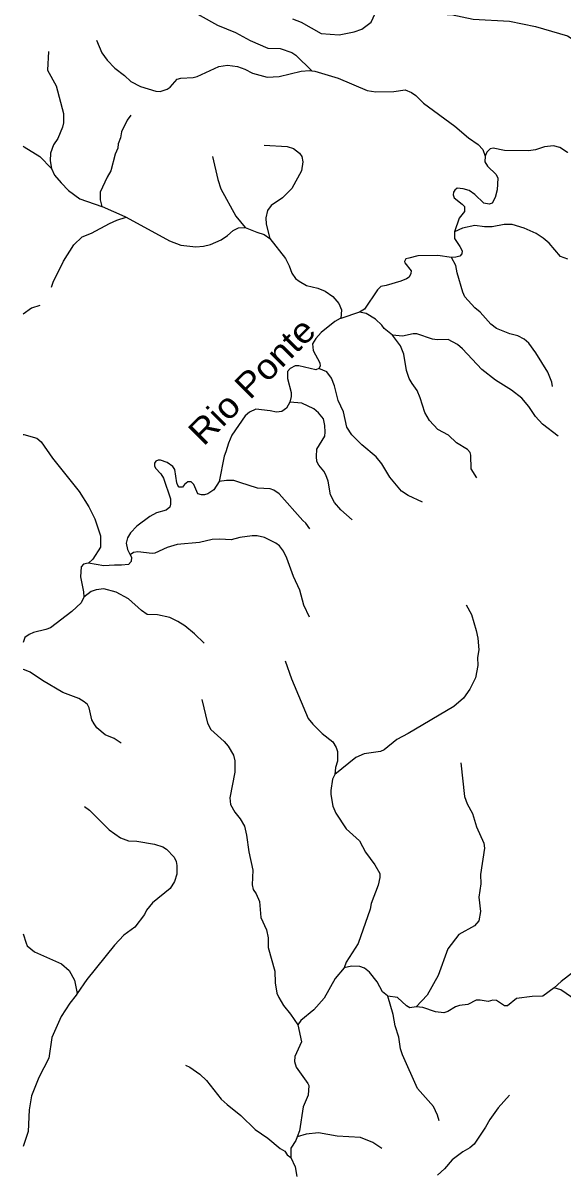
# Model space of a CAD drawing. Extents: x 500 to 555.2, y 9115.7 to 9171.
# Drawn here: x 500 to 504.32, y 9134.05 to 9143.26 of the extents above; entities that cross this region are included whole.
import ezdxf
from ezdxf.enums import TextEntityAlignment as Align

# ---------------------------------------------------------------- set-up
doc = ezdxf.new("R2010")
doc.units = 0
doc.header["$LTSCALE"] = 0.064
doc.layers.add('61', color=7, linetype='Continuous')
doc.layers.add('7', color=7, linetype='Continuous', lineweight=25)

msp = doc.modelspace()

# ---------------------------------------------------------------- linework, layer by layer
at = {"layer": '7'}
msp.add_line((502.6927, 9140.945), (502.5427, 9140.8959), dxfattribs=at)
for points in [[(500.9643, 9143.5366), (501.0579, 9143.5305), (501.1576, 9143.5029), (501.2267, 9143.4603), (501.2676, 9143.4228), (501.4187, 9143.3194), (501.5573, 9143.2411), (501.7002, 9143.1826), (501.8179, 9143.119), (501.959, 9143.0594), (502.0573, 9143.0566), (502.1503, 9143.0247), (502.1825, 9143.0017), (502.31, 9142.8774)], [(502.8542, 9143.412), (502.8891, 9143.4424), (502.9235, 9143.4619), (502.9561, 9143.4585), (503.0448, 9143.4339), (503.1768, 9143.3778), (503.2922, 9143.3451), (503.3952, 9143.3276), (503.4261, 9143.3272), (503.6025, 9143.2914), (503.8938, 9143.275), (504.1004, 9143.2307), (504.3557, 9143.1571), (504.3933, 9143.1335), (504.4178, 9143.1014)], [(502.1551, 9143.2942), (502.2264, 9143.2652), (502.3865, 9143.1751), (502.5297, 9143.1636), (502.6498, 9143.1896), (502.7101, 9143.2098), (502.7848, 9143.2671), (502.8536, 9143.4115), (502.8542, 9143.412)], [(500.5867, 9143.1233), (500.631, 9143.0212), (500.6726, 9142.9631), (500.7333, 9142.8992), (500.8115, 9142.8391), (500.8622, 9142.7924), (500.9402, 9142.7501), (501.0617, 9142.7131), (501.0961, 9142.7109), (501.1545, 9142.729), (501.1774, 9142.7469), (501.2345, 9142.8095), (501.2629, 9142.8174), (501.3612, 9142.8223), (501.3934, 9142.8304), (501.5664, 9142.9103), (501.6364, 9142.9208), (501.7169, 9142.9104), (501.7751, 9142.8893), (501.8361, 9142.8592), (501.9523, 9142.8273), (502.0483, 9142.8324), (502.2247, 9142.8749), (502.2911, 9142.8791), (502.31, 9142.8774)], [(500.2035, 9143.0302), (500.1964, 9142.8826), (500.2654, 9142.7567), (500.3245, 9142.5363), (500.3245, 9142.4609), (500.3164, 9142.4257), (500.2791, 9142.3348), (500.243, 9142.2836), (500.2187, 9142.2184), (500.2159, 9142.1567), (500.2278, 9142.095)], [(502.31, 9142.8774), (502.335, 9142.8751), (502.5207, 9142.8185), (502.755, 9142.72), (502.8243, 9142.7075), (502.968, 9142.7107), (503.0588, 9142.7237), (503.1091, 9142.7028), (503.1425, 9142.6795), (503.2038, 9142.6185), (503.4558, 9142.4351), (503.5636, 9142.3405), (503.6412, 9142.2875), (503.6782, 9142.2467), (503.6993, 9142.195)], [(500.8621, 9142.5208), (500.8342, 9142.4818), (500.7891, 9142.3899), (500.7788, 9142.3401), (500.7613, 9142.292), (500.7574, 9142.2581), (500.7379, 9142.2088), (500.7032, 9142.0769), (500.6728, 9142.0263), (500.618, 9141.9048), (500.6171, 9141.8451), (500.6318, 9141.792)], [(499.9999, 9142.2741), (500.0094, 9142.2682), (500.1338, 9142.1912), (500.2278, 9142.095)], [(501.929, 9142.2829), (502.1124, 9142.2711), (502.1654, 9142.2544), (502.2136, 9142.218), (502.2305, 9142.1907), (502.2402, 9142.1478), (502.2272, 9142.0777), (502.1504, 9141.9355), (502.0768, 9141.8614), (501.9858, 9141.7984), (501.9552, 9141.7582), (501.9437, 9141.7009), (501.9452, 9141.6485), (501.9743, 9141.5355)], [(504.3582, 9142.2248), (504.3555, 9142.2239), (504.2955, 9142.2628), (504.2448, 9142.2776), (504.1727, 9142.2695), (504.1004, 9142.2434), (504.0459, 9142.2357), (503.8529, 9142.2404), (503.7609, 9142.2579), (503.7389, 9142.2514), (503.712, 9142.2255), (503.6993, 9142.195)], [(501.5172, 9142.1907), (501.5584, 9142.0068), (501.5829, 9141.9328), (501.7027, 9141.7129), (501.778, 9141.622)], [(503.6993, 9142.195), (503.6983, 9142.1927), (503.6966, 9142.1481), (503.7155, 9142.1132), (503.7848, 9142.0471), (503.7986, 9142.017), (503.7937, 9141.9234), (503.7783, 9141.863), (503.754, 9141.8185), (503.7307, 9141.8088), (503.6873, 9141.8187), (503.6166, 9141.8873), (503.5709, 9141.9203), (503.5225, 9141.9333), (503.4736, 9141.9365), (503.4555, 9141.9219), (503.4445, 9141.9063), (503.4423, 9141.8857), (503.4502, 9141.86), (503.5148, 9141.8099), (503.5328, 9141.7913), (503.5331, 9141.7506), (503.4906, 9141.6972), (503.452, 9141.5873)], [(500.2278, 9142.095), (500.2527, 9142.0415), (500.3044, 9141.9798), (500.3651, 9141.9192), (500.4544, 9141.8521), (500.6318, 9141.792)], [(500.6318, 9141.792), (500.6335, 9141.7914), (500.8141, 9141.7118), (500.8242, 9141.7063)], [(500.227, 9141.1455), (500.24, 9141.1854), (500.323, 9141.3541), (500.4066, 9141.4854), (500.4726, 9141.5471), (500.5476, 9141.5776), (500.6925, 9141.6563), (500.7518, 9141.6826), (500.8242, 9141.7063)], [(500.8242, 9141.7063), (501.1729, 9141.5174), (501.2621, 9141.4808), (501.3815, 9141.4675), (501.4447, 9141.4742), (501.5008, 9141.4883), (501.5865, 9141.5252), (501.6351, 9141.5577), (501.6821, 9141.5999), (501.7235, 9141.6195), (501.7766, 9141.6225), (501.778, 9141.622)], [(501.778, 9141.622), (501.8701, 9141.5865), (501.9299, 9141.5675), (501.9743, 9141.5355)], [(503.452, 9141.5873), (503.4525, 9141.5354), (503.4955, 9141.4717), (503.5128, 9141.4353), (503.5124, 9141.4127), (503.495, 9141.3947), (503.4634, 9141.3861), (503.4295, 9141.383)], [(504.3597, 9141.3691), (504.3001, 9141.3911), (504.2101, 9141.4969), (504.1621, 9141.5383), (504.107, 9141.5756), (504.0092, 9141.6181), (503.9141, 9141.646), (503.8493, 9141.6464), (503.7527, 9141.6282), (503.6937, 9141.6282), (503.615, 9141.6379), (503.5172, 9141.6169), (503.452, 9141.5873)], [(501.9743, 9141.5355), (502.1009, 9141.3756), (502.1302, 9141.3171), (502.15, 9141.2582), (502.1808, 9141.2155), (502.2089, 9141.1927), (502.2686, 9141.1597), (502.3585, 9141.1377), (502.4175, 9141.113), (502.4798, 9141.0718), (502.5276, 9141.0143), (502.5483, 9140.9641), (502.5427, 9140.8959)], [(503.4295, 9141.383), (503.4286, 9141.3829), (503.3197, 9141.4001), (503.158, 9141.3958), (503.0865, 9141.3782), (503.0634, 9141.3717), (503.0535, 9141.3519), (503.0559, 9141.3395), (503.1048, 9141.2774), (503.1044, 9141.2537), (503.0897, 9141.2267), (503.0697, 9141.213), (503.0238, 9141.1934), (502.9057, 9141.1588), (502.8624, 9141.1509), (502.8374, 9141.1241), (502.7321, 9140.9695), (502.6927, 9140.945)], [(504.2379, 9140.3506), (504.2316, 9140.3848), (504.1998, 9140.4647), (504.1042, 9140.6211), (504.0467, 9140.6961), (504.0106, 9140.7288), (503.9588, 9140.7557), (503.8959, 9140.7723), (503.7878, 9140.8138), (503.7446, 9140.8491), (503.6571, 9140.9446), (503.6145, 9140.9807), (503.5362, 9141.0689), (503.5188, 9141.105), (503.4737, 9141.2614), (503.4624, 9141.3192), (503.4295, 9141.383)], [(500.1338, 9140.998), (500.0679, 9140.9767), (499.9999, 9140.93)], [(502.9554, 9140.7613), (502.8891, 9140.8157), (502.8698, 9140.8412), (502.8193, 9140.8883), (502.7445, 9140.934), (502.6927, 9140.945)], [(502.5427, 9140.8959), (502.5384, 9140.8945), (502.4948, 9140.872), (502.3864, 9140.7817), (502.3421, 9140.7358)], [(504.2831, 9139.9519), (504.1555, 9140.0494), (504.0997, 9140.1103), (504.0478, 9140.1912), (503.9904, 9140.2582), (503.909, 9140.3222), (503.7806, 9140.4014), (503.6719, 9140.4872), (503.516, 9140.6526), (503.4771, 9140.6866), (503.4019, 9140.7276), (503.3131, 9140.7245), (503.2777, 9140.7282), (503.1509, 9140.772), (503.1222, 9140.7733), (503.0358, 9140.7541), (502.9554, 9140.7613)], [(503.6305, 9139.6189), (503.5872, 9139.6927), (503.582, 9139.8015), (503.5767, 9139.8215), (503.5578, 9139.8464), (503.4684, 9139.8997), (503.4042, 9139.9599), (503.3197, 9140.0076), (503.2514, 9140.0782), (503.2162, 9140.1427), (503.1784, 9140.2608), (503.1543, 9140.3186), (503.1126, 9140.3757), (503.0911, 9140.4158), (503.069, 9140.4794), (503.0459, 9140.6106), (503.0197, 9140.6755), (502.9564, 9140.7605), (502.9554, 9140.7613)], [(502.3421, 9140.7358), (502.3171, 9140.6929), (502.3229, 9140.6394), (502.3747, 9140.5398), (502.378, 9140.5126), (502.3668, 9140.4944)], [(502.3668, 9140.4944), (502.3434, 9140.4853), (502.2071, 9140.5155), (502.1785, 9140.5161), (502.1369, 9140.4942), (502.1175, 9140.4694), (502.1157, 9140.414), (502.145, 9140.3035), (502.1449, 9140.2716), (502.135, 9140.2241)], [(503.1964, 9139.4238), (503.0813, 9139.4772), (503.0295, 9139.5119), (502.9339, 9139.6258), (502.8716, 9139.7325), (502.8268, 9139.7885), (502.7103, 9139.8837), (502.6305, 9139.9636), (502.591, 9140.0255), (502.5635, 9140.1486), (502.5223, 9140.2379), (502.4925, 9140.3567), (502.469, 9140.4162), (502.4305, 9140.4684), (502.3668, 9140.4944)], [(502.135, 9140.2241), (502.1074, 9140.1773), (502.0699, 9140.1506), (502.0279, 9140.1455), (501.9779, 9140.1568), (501.8642, 9140.1683), (501.8135, 9140.145), (501.7779, 9140.1158), (501.6701, 9139.9603), (501.6445, 9139.8983), (501.6236, 9139.8272), (501.6103, 9139.7937), (501.5688, 9139.5891)], [(502.6337, 9139.2848), (502.5443, 9139.3641), (502.4917, 9139.4231), (502.4601, 9139.4835), (502.4407, 9139.593), (502.424, 9139.6434), (502.4064, 9139.674), (502.3664, 9139.7201), (502.3521, 9139.7495), (502.3471, 9139.7916), (502.3518, 9139.8495), (502.4141, 9139.9541), (502.4189, 9139.9854), (502.4159, 9140.0391), (502.404, 9140.091), (502.365, 9140.1404), (502.3262, 9140.171), (502.2305, 9140.2174), (502.135, 9140.2241)], [(499.9999, 9139.9675), (500.0052, 9139.966), (500.1105, 9139.9371), (500.1439, 9139.9091), (500.2348, 9139.7774), (500.4504, 9139.5095), (500.5268, 9139.3865), (500.5738, 9139.2924), (500.6212, 9139.1553), (500.6193, 9139.0638), (500.5575, 9138.9687), (500.5234, 9138.9374)], [(501.5688, 9139.5891), (501.5256, 9139.5224), (501.4787, 9139.4924), (501.4521, 9139.4828), (501.4275, 9139.4827), (501.3989, 9139.4914), (501.3667, 9139.5667), (501.3446, 9139.5873), (501.3195, 9139.5886), (501.2925, 9139.5663), (501.2769, 9139.5451), (501.2655, 9139.5438), (501.2501, 9139.544), (501.2383, 9139.5583), (501.2299, 9139.5785), (501.2153, 9139.6854), (501.1977, 9139.7101), (501.1538, 9139.742), (501.0993, 9139.7613), (501.0803, 9139.7611), (501.0631, 9139.7522), (501.0531, 9139.7378), (501.0525, 9139.716), (501.0593, 9139.6966), (501.1015, 9139.652), (501.1251, 9139.6166), (501.1807, 9139.4525), (501.1808, 9139.4091), (501.1737, 9139.384), (501.1444, 9139.3598), (501.0693, 9139.3383), (501.0145, 9139.3106), (500.9113, 9139.2329), (500.861, 9139.1808), (500.8362, 9139.1407), (500.8265, 9139.0982), (500.8362, 9139.0468), (500.8562, 9139.0048)], [(502.2953, 9139.2107), (502.2632, 9139.2564), (502.238, 9139.2786), (502.05, 9139.4925), (502.0069, 9139.5213), (501.9766, 9139.5319), (501.8758, 9139.5383), (501.7351, 9139.5827), (501.6874, 9139.5979), (501.6277, 9139.5993), (501.5688, 9139.5891)], [(502.2934, 9138.5034), (502.2481, 9138.5997), (502.2148, 9138.7198), (502.1645, 9138.8309), (502.1107, 9138.9774), (502.0842, 9139.0338), (502.0529, 9139.0745), (502.0235, 9139.0979), (501.932, 9139.1431), (501.8729, 9139.1546), (501.8336, 9139.1562), (501.7351, 9139.1414), (501.665, 9139.1236), (501.5756, 9139.1284), (501.5122, 9139.125), (501.4126, 9139.1026), (501.2344, 9139.0868), (501.1546, 9139.0627), (501.0547, 9139.0166), (501.0325, 9139.0137), (500.9177, 9139.0266), (500.8846, 9139.0233), (500.8562, 9139.0048)], [(500.8562, 9139.0048), (500.8671, 9138.9844), (500.8642, 9138.951), (500.844, 9138.9269), (500.7886, 9138.9217), (500.7318, 9138.922), (500.6459, 9138.9151), (500.5234, 9138.9374)], [(500.5234, 9138.9374), (500.5216, 9138.9377), (500.4837, 9138.9276), (500.4664, 9138.9065), (500.4607, 9138.8265), (500.4836, 9138.7082), (500.4869, 9138.6646)], [(501.4504, 9138.2971), (501.3731, 9138.3717), (501.296, 9138.4357), (501.2398, 9138.4705), (501.1748, 9138.5014), (501.0757, 9138.5231), (500.9922, 9138.5267), (500.9469, 9138.5583), (500.8433, 9138.6507), (500.7464, 9138.7044), (500.6472, 9138.7312), (500.5856, 9138.7235), (500.5449, 9138.7104), (500.4869, 9138.6646)], [(500.4869, 9138.6646), (500.4639, 9138.6189), (500.3915, 9138.5505), (500.2195, 9138.4198), (500.1828, 9138.4049), (500.0844, 9138.3833), (500.0484, 9138.3668), (500.0153, 9138.3418), (500.0067, 9138.3189), (499.9999, 9138.3008)], [(503.5453, 9138.6027), (503.5873, 9138.5269), (503.6262, 9138.3992), (503.6397, 9138.3366), (503.6462, 9138.243), (503.6379, 9138.1809), (503.6395, 9138.1175), (503.6206, 9138.0202), (503.5745, 9137.9272), (503.5242, 9137.8571), (503.4464, 9137.7902), (503.0816, 9137.5741), (502.9922, 9137.5262), (502.8893, 9137.4436), (502.8604, 9137.4308), (502.7299, 9137.4112), (502.6636, 9137.3814), (502.4958, 9137.2443)], [(500.785, 9137.496), (500.7287, 9137.535), (500.6565, 9137.5636), (500.5903, 9137.6194), (500.5703, 9137.6513), (500.5512, 9137.6844), (500.5281, 9137.7795), (500.5151, 9137.8064), (500.4901, 9137.826), (500.4475, 9137.8538), (500.3185, 9137.9021), (500.1568, 9137.9969), (500.0561, 9138.0644), (500.0113, 9138.082), (499.9999, 9138.0865)], [(502.098, 9138.1557), (502.1479, 9138.0101), (502.2824, 9137.6927), (502.3183, 9137.6479), (502.393, 9137.5748), (502.4782, 9137.5077), (502.5059, 9137.4617), (502.5159, 9137.4292), (502.5169, 9137.3518), (502.5009, 9137.301), (502.4958, 9137.2443)], [(501.4297, 9137.8468), (501.4749, 9137.6577), (501.5034, 9137.6066), (501.6104, 9137.5094), (501.6404, 9137.4726), (501.6833, 9137.4005), (501.6943, 9137.3545), (501.694, 9137.2651), (501.6551, 9137.0597), (501.6601, 9137.0058), (501.6935, 9136.9446), (501.7388, 9136.8921), (501.7728, 9136.8321), (501.788, 9136.7608), (501.8056, 9136.6267), (501.8401, 9136.4803), (501.8337, 9136.3614), (501.842, 9136.3252), (501.8645, 9136.2911), (501.8925, 9136.2299), (501.9041, 9136.1011), (501.9489, 9136.0026), (501.9614, 9135.9396), (501.9609, 9135.8607), (502.0138, 9135.6713), (502.0175, 9135.5795), (502.0316, 9135.495), (502.0456, 9135.4602), (502.0842, 9135.3973), (502.1413, 9135.3281), (502.2002, 9135.2434)], [(503.5025, 9137.3401), (503.5336, 9137.0693), (503.5531, 9137.0112), (503.5954, 9136.9331), (503.6291, 9136.8258), (503.6868, 9136.6948), (503.6936, 9136.6549), (503.6609, 9136.4442), (503.6624, 9136.3714), (503.6462, 9136.2644), (503.6607, 9136.1504), (503.6474, 9136.0742), (503.612, 9136.0337), (503.487, 9135.9651), (503.399, 9135.8518), (503.321, 9135.6372), (503.235, 9135.4792), (503.1457, 9135.3873)], [(502.4958, 9137.2443), (502.4753, 9137.209), (502.4619, 9137.1174), (502.4621, 9137.0852), (502.4781, 9136.9934), (502.5025, 9136.9374), (502.586, 9136.8096), (502.6929, 9136.7154), (502.7391, 9136.6254), (502.8146, 9136.5225), (502.8538, 9136.4532), (502.8538, 9136.4219), (502.8424, 9136.3603), (502.7852, 9136.2125), (502.7765, 9136.1687), (502.6813, 9135.8945), (502.5852, 9135.7434), (502.5691, 9135.6974)], [(500.4913, 9136.9896), (500.5315, 9136.961), (500.6894, 9136.8017), (500.7806, 9136.7386), (500.845, 9136.7158), (500.9112, 9136.7122), (501.0523, 9136.6877), (501.1175, 9136.6667), (501.1476, 9136.6469), (501.2081, 9136.5831), (501.2265, 9136.5498), (501.2315, 9136.5177), (501.2294, 9136.4487), (501.2116, 9136.3885), (501.1768, 9136.3345), (501.0359, 9136.2196), (500.9893, 9136.16), (500.972, 9136.1261), (500.8937, 9136.025), (500.8055, 9135.9612), (500.7307, 9135.8802), (500.5115, 9135.605), (500.4341, 9135.4932)], [(499.9999, 9135.9715), (500.0255, 9135.8951), (500.032, 9135.8757), (500.0916, 9135.8266), (500.3081, 9135.7296), (500.3692, 9135.6783), (500.4123, 9135.5992), (500.4341, 9135.4932)], [(504.5983, 9135.823), (504.5971, 9135.8212), (504.5296, 9135.7616), (504.3051, 9135.5896), (504.2502, 9135.5373)], [(502.5691, 9135.6974), (502.4969, 9135.6123), (502.4105, 9135.4569), (502.3261, 9135.3627), (502.2224, 9135.2769), (502.2002, 9135.2434)], [(502.9203, 9135.4729), (502.9169, 9135.4734), (502.8754, 9135.5067), (502.8337, 9135.5857), (502.7734, 9135.6641), (502.7324, 9135.6967), (502.6958, 9135.7101), (502.6288, 9135.7129), (502.5691, 9135.6974)], [(500.4341, 9135.4932), (500.4248, 9135.4797), (500.3743, 9135.4166), (500.3058, 9135.3095), (500.2316, 9135.1407), (500.2062, 9134.9746), (500.127, 9134.8197), (500.0687, 9134.6733), (500.0503, 9134.563), (500.0409, 9134.3894), (499.9999, 9134.2678)], [(504.2502, 9135.5373), (504.1589, 9135.4709), (504.0746, 9135.468), (503.9475, 9135.4527), (503.8777, 9135.3935), (503.8532, 9135.3956), (503.7881, 9135.4361), (503.7597, 9135.4404), (503.7217, 9135.4297), (503.6576, 9135.4409), (503.6249, 9135.4391), (503.5591, 9135.4051), (503.4929, 9135.3965), (503.4614, 9135.3854), (503.399, 9135.3479), (503.3663, 9135.3396), (503.3015, 9135.3472), (503.1998, 9135.3806), (503.1457, 9135.3873)], [(504.4244, 9135.4394), (504.304, 9135.5213), (504.2502, 9135.5373)], [(503.3293, 9134.4737), (503.3177, 9134.5199), (503.2839, 9134.5875), (503.1566, 9134.732), (503.0372, 9135.0015), (503.0215, 9135.0493), (503.008, 9135.1425), (502.9786, 9135.2337), (502.9622, 9135.3248), (502.9203, 9135.4729)], [(503.0692, 9135.3944), (502.9965, 9135.4622), (502.9203, 9135.4729)], [(503.1457, 9135.3873), (503.0961, 9135.3775), (503.0692, 9135.3944)], [(502.2002, 9135.2434), (502.227, 9135.1065), (502.175, 9134.9888), (502.1733, 9134.9483), (502.1849, 9134.9029), (502.2795, 9134.7719), (502.2862, 9134.7557), (502.2811, 9134.6794), (502.2403, 9134.5874), (502.2125, 9134.3945), (502.1933, 9134.345)], [(501.2988, 9134.9207), (501.3355, 9134.9042), (501.4149, 9134.8476), (501.469, 9134.7966), (501.5862, 9134.6473), (501.6327, 9134.6037), (501.7429, 9134.5163), (501.8573, 9134.4052), (501.9587, 9134.3351), (502.0567, 9134.2536), (502.0956, 9134.2304), (502.1123, 9134.203), (502.1428, 9134.1799)], [(503.8939, 9134.6791), (503.8007, 9134.5787), (503.735, 9134.4859), (503.7002, 9134.4241), (503.61, 9134.2879), (503.5763, 9134.2576), (503.5204, 9134.2248), (503.4346, 9134.1615), (503.3738, 9134.0895), (503.3168, 9134.0389)], [(502.1933, 9134.345), (502.1825, 9134.3173), (502.1442, 9134.2541), (502.1418, 9134.182), (502.1428, 9134.1799)], [(502.8712, 9134.2519), (502.8001, 9134.2999), (502.6991, 9134.342), (502.5146, 9134.3516), (502.365, 9134.378), (502.2661, 9134.3681), (502.1933, 9134.345)], [(502.1428, 9134.1799), (502.178, 9134.1058), (502.191, 9134.0279)]]:
    msp.add_lwpolyline(points, dxfattribs=at)

# ---------------------------------------------------------------- texts
at = {"layer": '61', "width": 1.1}
msp.add_text('Rio Ponte', height=0.2, rotation=45, dxfattribs=at).set_placement((501.9012, 9140.3242), align=Align.CENTER)

doc.saveas('drawing.dxf')
